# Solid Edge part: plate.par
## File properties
Author: Deepak Maini
Template: Normal.par
Last saved by: Robert a Rhodes jr
Revision: 1
Application: Solid Edge
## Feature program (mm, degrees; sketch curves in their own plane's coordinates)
sketch for "unnamed Protrusion 1" plane through (0, 0, 0) normal (0, 0, 1) x-axis (1, 0, 0)
  circle centre (0, 0) radius 59.0444
extrude "unnamed Protrusion 1" add finite 19.05 along -normal
sketch for "unnamed Hole 1" plane through (0, 0, 0) normal (0, 0, 1) x-axis (0, 1, 0)
  hole centre (-28.483, 27.7745) bore radius 8
hole "unnamed Hole 1" through
sketch for "unnamed Cutout 1" plane through (0, 0, 0) normal (0, 0, 1) x-axis (0, 1, 0)
  line (-59.0916, 45.0627) -> (-29.6658, 45.0627)
  arc centre (-29.6658, 29.4258) radius 15.6369 from (-29.6658, 45.0627) to (-14.0289, 29.4258) cw
  line (-14.0289, 29.4258) -> (-14.0289, 27.7745)
  arc centre (-28.483, 27.7745) radius 14.4541 from (-14.0289, 27.7745) to (-28.483, 13.3204) cw
  line (-28.483, 13.3204) -> (-59.0916, 13.3204)
  line (-59.0916, 13.3204) -> (-59.0916, 45.0627)
extrude "unnamed Cutout 1" cut finite 6.35 along -normal
pattern "unnamed Pattern 1" of "unnamed Hole 1"
hole "unnamed Hole 2" through
hole "unnamed Hole 3" through
hole "unnamed Hole 4" through
mirror "unnamed Mirror 1" of "unnamed Cutout 1" about plane through (0, 0, 0) normal (0, -1, 0)
extrude "unnamed Cutout 2" cut finite 6.35
mirror "unnamed Mirror 2" of "unnamed Cutout 1" about plane through (0, 0, 0) normal (1, 0, 0)
extrude "unnamed Cutout 3" cut finite 6.35
mirror "unnamed Mirror 3" of "unnamed Mirror 1" about plane through (0, 0, 0) normal (1, 0, 0)
extrude "unnamed Cutout 4" cut finite 6.35
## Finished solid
Body 1: solid body, 31 faces, 81 edges, 48 vertices.
  Faces by surface: plane 18, cylinder 13
  Edges by curve: line 48, circle 33
Bounding box of the edges (mm): 118.089 x 118.089 x 19.050, from (-59.0444, -59.0444, -19.05) to (59.0444, 59.0444, 0).
Cylindrical faces by radius (mm): R8 x4, R14.4541 x4, R15.6369 x4, R59.0444 x1
Planar faces by outward normal: +x 4, +y 2, +z 5, -x 4, -y 2, -z 1
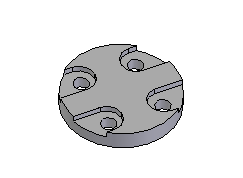
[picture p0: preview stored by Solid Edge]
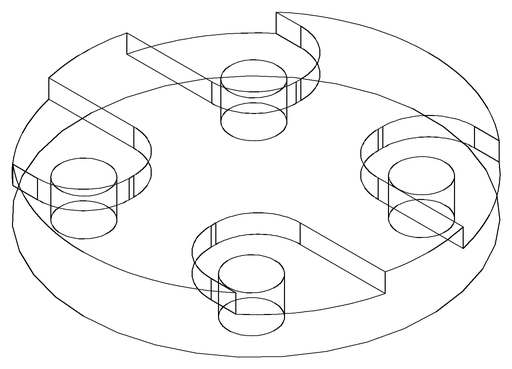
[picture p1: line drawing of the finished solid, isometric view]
